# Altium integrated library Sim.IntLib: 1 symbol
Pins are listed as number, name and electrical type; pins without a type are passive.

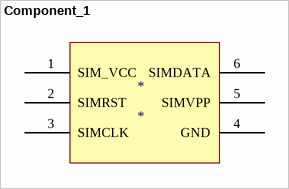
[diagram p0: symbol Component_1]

## Component_1
designator *
footprint SIM Holder
pins: 1 SIM_VCC, 2 SIMRST, 3 SIMCLK, 4 GND, 5 SIMVPP, 6 SIMDATA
